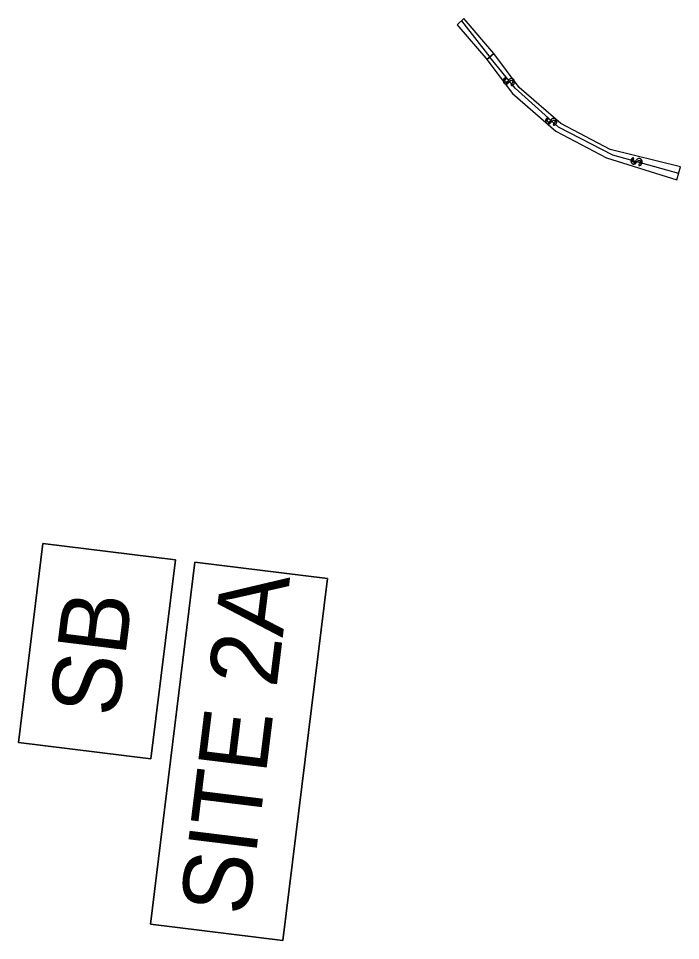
# Model space of a CAD drawing. Extents: x 474218 to 481634, y 484357 to 504997.
# Drawn here: x 481230.6 to 481375, y 491241.6 to 491442.8 of the extents above; entities that cross this region are included whole.
import ezdxf

# ---------------------------------------------------------------- set-up
doc = ezdxf.new("R2010")
doc.units = 0
for name, color, linetype in [('Exist Hydro Jurisdictional Stream or Body of Water', 7, 'Continuous'), ('Old_Level_29', 7, 'Continuous'), ('Prop Earthen Structure Impacts In Surface Waters Hatching CELL', 7, 'Continuous'), ('Prop Grid Mask', 7, 'Continuous'), ('Scratch_Level_4', 7, 'Continuous'), ('Temp Earthen Structure Impacts In Surface Waters Hatching CELL', 7, 'Continuous')]:
    doc.layers.add(name, color=color, linetype=linetype)

msp = doc.modelspace()

# ---------------------------------------------------------------- linework, layer by layer
at = {"layer": 'Exist Hydro Jurisdictional Stream or Body of Water'}
msp.add_lwpolyline([(481230.64, 491284.83), (481235.98, 491328.23), (481264.85, 491324.68), (481259.5, 491281.28)], close=True, dxfattribs=at)
at = {"layer": 'Old_Level_29'}
msp.add_lwpolyline([(481259.4, 491245.19), (481269.12, 491324.15), (481298, 491320.6), (481288.27, 491241.63)], close=True, dxfattribs=at)
at = {"layer": 'Prop Earthen Structure Impacts In Surface Waters Hatching CELL'}
msp.add_lwpolyline([(481374.17, 491407.56), (481374.98, 491410.45), (481359.65, 491414.18), (481348.89, 491419.88), (481339.81, 491427.76), (481334.25, 491435.18), (481332.76, 491433.83), (481338.33, 491426.39), (481347.76, 491418.22), (481358.83, 491412.35), (481374.17, 491407.56)], dxfattribs=at)
for points in [[(481336.91, 491428.49), (481337, 491428.48), (481337.09, 491428.91), (481337, 491428.88), (481336.87, 491428.9), (481336.86, 491428.9), (481336.83, 491428.92), (481336.75, 491428.97), (481336.73, 491429), (481336.7, 491429.06), (481336.69, 491429.08), (481336.69, 491429.1), (481336.69, 491429.16), (481336.68, 491429.24), (481336.81, 491429.88), (481336.77, 491429.87), (481336.63, 491429.79), (481336.6, 491429.77), (481336.46, 491429.59), (481336.35, 491429.02), (481336.41, 491428.83), (481336.43, 491428.78), (481336.52, 491428.67), (481336.56, 491428.64), (481336.57, 491428.62), (481336.59, 491428.6), (481336.59, 491428.6), (481336.61, 491428.59), (481336.64, 491428.58), (481336.67, 491428.56), (481336.75, 491428.52), (481336.78, 491428.51), (481336.79, 491428.51)], [(481336.35, 491429.05), (481336.35, 491429.02), (481336.46, 491429.59), (481336.46, 491429.59), (481336.36, 491429.31), (481336.36, 491429.31)], [(481336.87, 491429.52), (481336.96, 491429.57), (481336.91, 491429.75), (481336.9, 491429.81), (481336.87, 491429.89), (481336.86, 491429.89), (481336.85, 491429.89), (481336.83, 491429.88), (481336.81, 491429.88), (481336.68, 491429.24), (481336.73, 491429.4), (481336.75, 491429.42), (481336.76, 491429.42), (481336.78, 491429.45), (481336.84, 491429.5)], [(481338.42, 491429.02), (481338.42, 491428.87), (481338.55, 491429.51), (481338.53, 491429.53), (481338.53, 491429.53), (481338.52, 491429.54), (481338.48, 491429.58), (481338.47, 491429.59), (481338.45, 491429.59), (481338.39, 491429.62), (481338.36, 491429.63), (481338.34, 491429.64), (481338.26, 491429.68), (481338.2, 491429.68), (481338.07, 491429.7), (481338.01, 491429.7), (481337.96, 491429.69), (481337.86, 491429.65), (481337.86, 491429.65), (481337.78, 491429.63), (481337.73, 491429.58), (481337.59, 491429.46), (481337.55, 491429.42), (481337.4, 491429.24), (481337.33, 491429.14), (481337.21, 491428.53), (481337.26, 491428.56), (481337.39, 491428.65), (481337.43, 491428.68), (481337.58, 491428.85), (481337.64, 491428.93), (481337.74, 491429.06), (481337.86, 491429.21), (481337.92, 491429.25), (481337.98, 491429.29), (481338.12, 491429.31), (481338.17, 491429.29), (481338.26, 491429.26), (481338.28, 491429.25), (481338.31, 491429.22), (481338.37, 491429.18), (481338.38, 491429.15), (481338.39, 491429.12), (481338.42, 491429.04), (481338.42, 491429.03)], [(481337.15, 491428.51), (481337.21, 491428.53), (481337.33, 491429.14), (481337.26, 491429.04), (481337.13, 491428.93), (481337.09, 491428.91), (481337, 491428.48), (481337.04, 491428.49)], [(481338.64, 491428.48), (481338.76, 491428.78), (481338.77, 491429.12), (481338.77, 491429.12), (481338.68, 491429.37), (481338.66, 491429.4), (481338.55, 491429.51), (481338.42, 491428.87), (481338.36, 491428.7), (481338.36, 491428.7), (481338.35, 491428.69), (481338.28, 491428.61), (481338.26, 491428.58), (481338.24, 491428.57), (481338.16, 491428.53), (481338.13, 491428.51), (481338.1, 491428.51), (481338.01, 491428.49), (481338.06, 491428.29), (481338.07, 491428.24), (481338.09, 491428.17), (481338.16, 491428.18), (481338.18, 491428.18), (481338.19, 491428.18), (481338.24, 491428.18), (481338.25, 491428.19), (481338.25, 491428.19), (481338.28, 491428.2), (481338.43, 491428.27), (481338.45, 491428.28), (481338.64, 491428.47)], [(481346.14, 491419.79), (481346.22, 491419.78), (481346.31, 491420.21), (481346.22, 491420.18), (481346.09, 491420.2), (481346.08, 491420.2), (481346.05, 491420.22), (481345.98, 491420.27), (481345.96, 491420.31), (481345.93, 491420.36), (481345.91, 491420.38), (481345.91, 491420.4), (481345.91, 491420.46), (481345.91, 491420.54), (481346.04, 491421.18), (481345.99, 491421.17), (481345.86, 491421.09), (481345.83, 491421.07), (481345.69, 491420.89), (481345.57, 491420.33), (481345.63, 491420.14), (481345.65, 491420.09), (481345.75, 491419.98), (481345.78, 491419.94), (481345.8, 491419.92), (481345.81, 491419.91), (481345.81, 491419.9), (481345.83, 491419.9), (481345.87, 491419.88), (481345.89, 491419.86), (481345.97, 491419.83), (481346, 491419.81), (481346.01, 491419.81)], [(481345.57, 491420.35), (481345.57, 491420.33), (481345.69, 491420.89), (481345.68, 491420.89), (481345.58, 491420.61), (481345.58, 491420.61)], [(481346.09, 491420.82), (481346.19, 491420.87), (481346.14, 491421.05), (481346.12, 491421.11), (481346.1, 491421.19), (481346.08, 491421.19), (481346.08, 491421.19), (481346.06, 491421.18), (481346.04, 491421.18), (481345.91, 491420.54), (481345.96, 491420.7), (481345.98, 491420.72), (481345.98, 491420.73), (481346.01, 491420.75), (481346.06, 491420.81)], [(481346.38, 491419.82), (481346.43, 491419.83), (481346.56, 491420.44), (481346.49, 491420.34), (481346.36, 491420.23), (481346.31, 491420.21), (481346.22, 491419.78), (481346.27, 491419.79)], [(481347.65, 491420.32), (481347.64, 491420.17), (481347.78, 491420.81), (481347.75, 491420.83), (481347.75, 491420.84), (481347.75, 491420.84), (481347.71, 491420.88), (481347.69, 491420.89), (481347.68, 491420.89), (481347.61, 491420.92), (481347.59, 491420.93), (481347.56, 491420.94), (481347.48, 491420.98), (481347.43, 491420.99), (481347.29, 491421), (481347.23, 491421), (481347.18, 491420.99), (481347.09, 491420.96), (481347.09, 491420.96), (481347.01, 491420.93), (481346.95, 491420.88), (481346.81, 491420.76), (481346.78, 491420.72), (481346.63, 491420.54), (481346.56, 491420.44), (481346.43, 491419.83), (481346.49, 491419.87), (481346.62, 491419.95), (481346.65, 491419.99), (481346.8, 491420.15), (481346.87, 491420.24), (481346.96, 491420.36), (481347.09, 491420.51), (481347.14, 491420.55), (481347.21, 491420.59), (481347.35, 491420.61), (481347.4, 491420.59), (481347.48, 491420.56), (481347.51, 491420.55), (481347.53, 491420.53), (481347.59, 491420.48), (481347.6, 491420.45), (481347.61, 491420.42), (481347.64, 491420.34), (481347.65, 491420.33)], [(481347.87, 491419.78), (481347.98, 491420.09), (481348, 491420.42), (481348, 491420.42), (481347.9, 491420.67), (481347.89, 491420.7), (481347.78, 491420.81), (481347.64, 491420.17), (481347.58, 491420), (481347.58, 491420), (481347.57, 491419.99), (481347.51, 491419.91), (481347.48, 491419.88), (481347.47, 491419.87), (481347.39, 491419.83), (481347.35, 491419.81), (481347.33, 491419.81), (481347.24, 491419.79), (481347.28, 491419.59), (481347.3, 491419.54), (481347.31, 491419.47), (481347.38, 491419.48), (481347.4, 491419.48), (481347.42, 491419.48), (481347.47, 491419.49), (481347.47, 491419.49), (481347.48, 491419.49), (481347.5, 491419.5), (481347.66, 491419.57), (481347.67, 491419.58), (481347.86, 491419.78)], [(481364.75, 491411.02), (481364.84, 491411.01), (481364.93, 491411.44), (481364.83, 491411.41), (481364.7, 491411.43), (481364.69, 491411.43), (481364.66, 491411.45), (481364.59, 491411.5), (481364.57, 491411.54), (481364.54, 491411.59), (481364.52, 491411.61), (481364.52, 491411.63), (481364.52, 491411.69), (481364.52, 491411.77), (481364.65, 491412.41), (481364.6, 491412.4), (481364.47, 491412.32), (481364.44, 491412.3), (481364.3, 491412.13), (481364.18, 491411.56), (481364.24, 491411.37), (481364.26, 491411.32), (481364.36, 491411.21), (481364.39, 491411.17), (481364.41, 491411.15), (481364.42, 491411.14), (481364.42, 491411.13), (481364.44, 491411.13), (481364.48, 491411.11), (481364.5, 491411.1), (481364.58, 491411.06), (481364.61, 491411.04), (481364.62, 491411.04)], [(481364.18, 491411.59), (481364.18, 491411.56), (481364.3, 491412.13), (481364.29, 491412.12), (481364.19, 491411.84), (481364.19, 491411.84)], [(481364.7, 491412.05), (481364.8, 491412.1), (481364.75, 491412.28), (481364.73, 491412.34), (481364.71, 491412.42), (481364.69, 491412.42), (481364.69, 491412.42), (481364.67, 491412.41), (481364.65, 491412.41), (481364.52, 491411.77), (481364.57, 491411.93), (481364.59, 491411.95), (481364.59, 491411.96), (481364.62, 491411.98), (481364.67, 491412.04)], [(481364.99, 491411.05), (481365.04, 491411.06), (481365.17, 491411.67), (481365.1, 491411.57), (481364.97, 491411.46), (481364.93, 491411.44), (481364.84, 491411.01), (481364.88, 491411.02)], [(481366.26, 491411.55), (481366.25, 491411.4), (481366.39, 491412.04), (481366.36, 491412.07), (481366.36, 491412.07), (481366.36, 491412.07), (481366.32, 491412.11), (481366.3, 491412.12), (481366.29, 491412.12), (481366.22, 491412.15), (481366.2, 491412.16), (481366.17, 491412.17), (481366.09, 491412.21), (481366.04, 491412.22), (481365.9, 491412.23), (481365.85, 491412.24), (481365.79, 491412.22), (481365.7, 491412.19), (481365.7, 491412.19), (481365.62, 491412.16), (481365.56, 491412.11), (481365.42, 491411.99), (481365.39, 491411.95), (481365.24, 491411.77), (481365.17, 491411.67), (481365.04, 491411.06), (481365.1, 491411.1), (481365.23, 491411.18), (481365.26, 491411.22), (481365.41, 491411.38), (481365.48, 491411.47), (481365.57, 491411.59), (481365.7, 491411.74), (481365.75, 491411.78), (481365.82, 491411.82), (481365.96, 491411.84), (481366.01, 491411.82), (481366.1, 491411.79), (481366.12, 491411.78), (481366.14, 491411.76), (481366.2, 491411.71), (481366.21, 491411.68), (481366.22, 491411.65), (481366.25, 491411.57), (481366.26, 491411.56)], [(481366.48, 491411.01), (481366.59, 491411.32), (481366.61, 491411.65), (481366.61, 491411.65), (481366.51, 491411.9), (481366.5, 491411.93), (481366.39, 491412.04), (481366.25, 491411.4), (481366.19, 491411.23), (481366.19, 491411.23), (481366.18, 491411.22), (481366.12, 491411.14), (481366.09, 491411.11), (481366.08, 491411.1), (481366, 491411.06), (481365.96, 491411.04), (481365.94, 491411.04), (481365.85, 491411.02), (481365.89, 491410.82), (481365.91, 491410.77), (481365.92, 491410.7), (481366, 491410.71), (481366.01, 491410.71), (481366.03, 491410.71), (481366.08, 491410.72), (481366.09, 491410.72), (481366.09, 491410.72), (481366.11, 491410.73), (481366.27, 491410.8), (481366.29, 491410.81), (481366.47, 491411.01)]]:
    msp.add_lwpolyline(points, close=True, dxfattribs=at)
at = {"layer": 'Prop Grid Mask'}
for points in [[(481259.5, 491281.28), (481264.85, 491324.68), (481235.98, 491328.23), (481230.64, 491284.83)], [(481288.27, 491241.63), (481298, 491320.6), (481269.12, 491324.15), (481259.4, 491245.19)]]:
    msp.add_lwpolyline(points, close=True, dxfattribs=at)
at = {"layer": 'Scratch_Level_4'}
msp.add_line((481327.21, 491442.26), (481333.37, 491434.38), dxfattribs=at)
msp.add_lwpolyline([(481374.17, 491407.56), (481374.98, 491410.45), (481359.65, 491414.18), (481348.89, 491419.88), (481339.81, 491427.76), (481334.25, 491435.18), (481332.76, 491433.83), (481338.33, 491426.39), (481347.76, 491418.22), (481358.83, 491412.35)], close=True, dxfattribs=at)
msp.add_lwpolyline([(481374.58, 491409), (481360.25, 491412.94), (481348.34, 491419.08), (481338.95, 491427.56), (481333.37, 491434.38)], dxfattribs=at)
at = {"layer": 'Temp Earthen Structure Impacts In Surface Waters Hatching CELL'}
for p, q in [((481327.77, 491442.8), (481326.31, 491441.4)), ((481326.31, 491441.4), (481326.66, 491440.93))]:
    msp.add_line(p, q, dxfattribs=at)
msp.add_lwpolyline([(481326.66, 491440.93), (481332.55, 491434.11), (481332.76, 491433.83), (481334.25, 491435.18), (481328.23, 491442.17), (481327.77, 491442.8)], dxfattribs=at)

# ---------------------------------------------------------------- texts
at = {"layer": 'Exist Hydro Jurisdictional Stream or Body of Water'}
msp.add_text('SB', height=15, rotation=82.9799, dxfattribs=at).set_placement((481252.27, 491290.11))
at = {"layer": 'Old_Level_29'}
msp.add_text('SITE 2A', height=15, rotation=82.9799, dxfattribs=at).set_placement((481280.75, 491246.77))

doc.saveas('drawing.dxf')
